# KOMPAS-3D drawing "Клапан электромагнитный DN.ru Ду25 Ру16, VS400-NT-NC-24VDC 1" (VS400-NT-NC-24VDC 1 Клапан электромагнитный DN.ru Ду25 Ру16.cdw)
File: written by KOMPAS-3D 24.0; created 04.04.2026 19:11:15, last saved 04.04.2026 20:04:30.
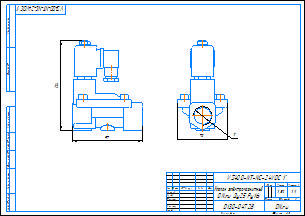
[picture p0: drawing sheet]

Document properties: c3d_UniqueCompID: ef56311e-7521-43dc-8291-0e6108b3d81d; Обозначение: VS400-ET-NC-220VAC 1; Наименование: Клапан электромагнитный DN.ru Ду25 Ру16; Автор: artio; Класс точности: c; Знак неуказанной шероховатости: Шероховатость не задана; Рассекать на разрезах: Да; c3d_UniqueCompID: ef56311e-7521-43dc-8291-0e6108b3d81d; Обозначение: VS400-ET-NC-220VAC 1-2; Наименование: Клапан электромагнитный DN.ru Ду15 Ру16; Автор: artio; Класс точности: c; Знак неуказанной шероховатости: Шероховатость не задана; Рассекать на разрезах: Да; c3d_UniqueCompID: ef56311e-7521-43dc-8291-0e6108b3d81d; Обозначение: VS400-ET-NC-220VAC 3-4; Наименование: Клапан электромагнитный DN.ru Ду20 Ру16; Автор: artio; Класс точности: c; Знак неуказанной шероховатости: Шероховатость не задана; Рассекать на разрезах: Да; c3d_UniqueCompID: ef56311e-7521-43dc-8291-0e6108b3d81d; Обозначение: VS400-ET-NC-220VAC 3-8; Наименование: Клапан электромагнитный DN.ru Ду10 Ру16; Автор: artio; Класс точности: c; Знак неуказанной шероховатости: Шероховатость не задана; Рассекать на разрезах: Да; Автор: artio; Форматы листов документа: A3; Полное имя файла: VS400-NT-NC-24VDC 1 Клапан электромагнитный DN.ru Ду25 Ру16.m3d; Масса: 1.524; Наименование: Клапан электромагнитный DN.ru Ду25 Ру16; Количество листов документа: 1; Примечание: D130-04728

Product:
- Body: Тело 1  | qty 1
    Масса: 1.76797
- Part/product: Клапан электромагнитный DN.ru Ду25 Ру16  | designation VS400-NT-NC-24VDC 1
    Масса: 1.524
    Раздел спецификации: Прочие изделия
    Примечание: D130-04728
    additional columns: ef56311e-7521-43dc-8291-0e6108b3d81d; VS400-ET-NC-220VAC 1; artio; c; Шероховатость не задана; Да

Views: Вид 1, Спереди
Referenced files in C:\Users\artio\OneDrive\Рабочий стол\Клапан электромагнитный DN.ru\VS400-ET-NC\VS400-ET-NC-24VDC\: VS400-ET-NC-24VDC 3-8 Клапан электромагнитный DN.ru Ду10 Ру16.m3d
Referenced files in C:\Users\artio\OneDrive\Рабочий стол\Клапан электромагнитный DN.ru\VS400-NT-NC\VS400-NT-NC-24VDC\: VS400-NT-NC-24VDC 1 Клапан электромагнитный DN.ru Ду25 Ру16.m3d
Referenced files in C:\Users\artio\OneDrive\Рабочий стол\Клапан электромагнитный DN.ru\VS400-ET-NC\: VS400-ET-NC-24VDC 3-8 Клапан электромагнитный DN.ru Ду10 Ру16.cdw
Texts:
  VS400-NT-NC-24VDC 1
  Клапан электромагнитный
  DN.ru Ду25 Ру16
  VS400-NT-NC-24VDC 1"
  VS400-NT-NC-24VDC 1"-
  Клапан электромагнитный DN.ru Ду25 Ру16
  VS400-NT-NC-24VDC 1 Клапан электромагнитный DN.ru Ду25 Ру16
Dimensions and other numbers on the sheet: 0; 3; 2; 4; 70; 1:1; 1; 1,52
